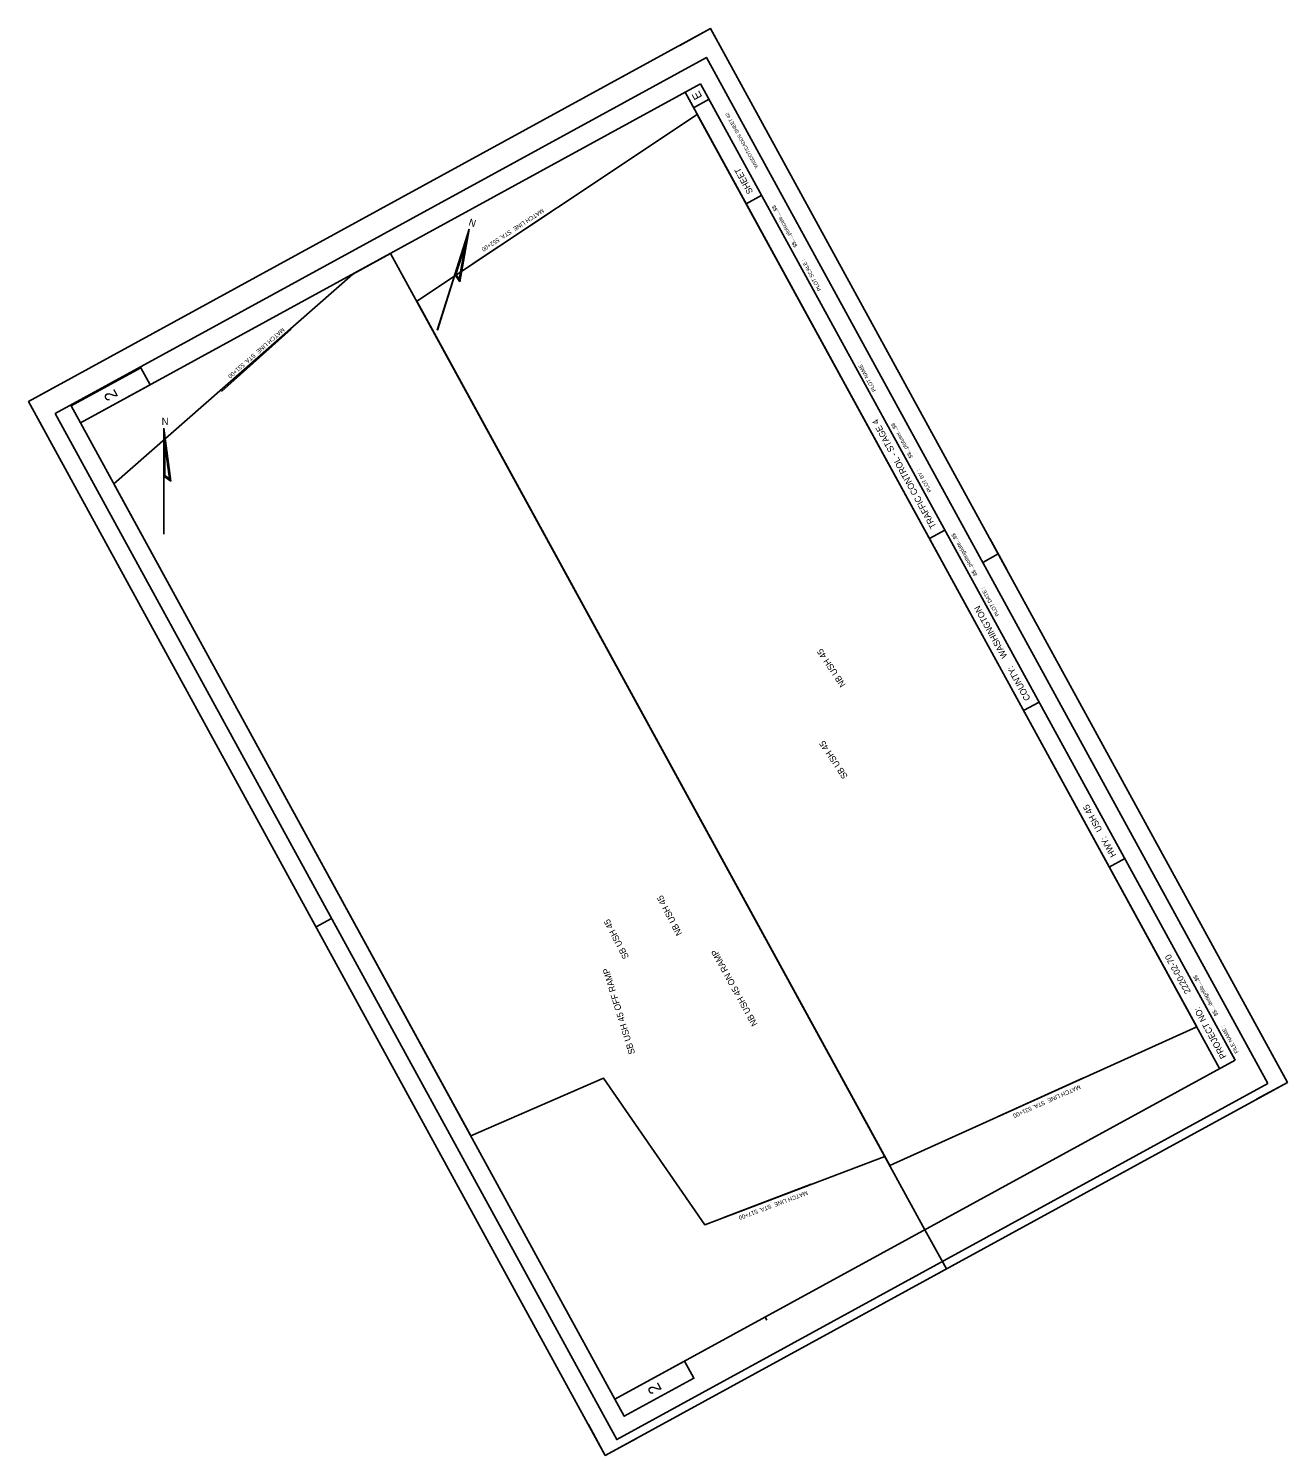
# Model space of a CAD drawing. Extents: x 358820 to 360601, y 175646 to 177665.
import ezdxf

# ---------------------------------------------------------------- set-up
doc = ezdxf.new("R2010")
doc.units = 0
for name, color, linetype in [('Default', 7, 'Continuous'), ('P_ALI_20', 7, 'Continuous'), ('P_ALI_200_Sta', 7, 'Continuous'), ('P_ALI_20_PIData', 7, 'Continuous'), ('P_ALI_20_Sta', 7, 'Continuous'), ('P_ALI_20_Tic', 7, 'Continuous'), ('P_ALI_50_Equation', 7, 'Continuous'), ('P_ALI_50_PIData', 7, 'Continuous'), ('P_ALI_50_Tic', 7, 'Continuous')]:
    doc.layers.add(name, color=color, linetype=linetype)

msp = doc.modelspace()

# ---------------------------------------------------------------- linework, layer by layer
msp.add_lwpolyline([(359635.8, 175645.7), (358819.8, 177137.1), (359784.8, 177665), (360600.8, 176173.7), (359635.8, 175645.7)])
at = {"layer": 'Default'}
for points in [[(360038.2, 176056.2), (360472.4, 176252.1), (359765.9, 177543.3), (359368.9, 177279.4)], [(360038.2, 176056.2), (360472.4, 176252.1), (359765.9, 177543.3), (359368.9, 177279.4)], [(360038.2, 176056.2), (360472.4, 176252.1), (359765.9, 177543.3), (359368.9, 177279.4)], [(359445.4, 176097.8), (359633.3, 176179.8), (359776.4, 175972.2), (360031.1, 176069), (359332, 177346.9), (359278.5, 177317.6), (358940.5, 177020.6)], [(359445.4, 176097.8), (359633.3, 176179.8), (359776.4, 175972.2), (360031.1, 176069), (359332, 177346.9), (359278.5, 177317.6), (358940.5, 177020.6)]]:
    msp.add_lwpolyline(points, close=True, dxfattribs=at)
at = {"layer": 'P_ALI_20'}
for p, q in [((359784.8, 177665), (359741, 177641)), ((359808.8, 177621.2), (359784.8, 177665)), ((359770.6, 177586.9), (358893.3, 177106.9)), ((360526.6, 176205.2), (359770.6, 177586.9)), ((360504.6, 176193.2), (359748.7, 177574.9)), ((359782.6, 177564.9), (359760.7, 177552.9)), ((359857, 177429), (359835.1, 177417)), ((360087.9, 175965.2), (359332, 177346.9)), ((358863.7, 177161.1), (358819.8, 177137.1)), ((358843.8, 177093.2), (358819.8, 177137.1)), ((359649.3, 175725.2), (358893.3, 177106.9)), ((360116.2, 176955.2), (360094.3, 176943.2)), ((360203.6, 176899.6), (360179.6, 176943.5)), ((360191.6, 176921.5), (360169.7, 176909.5)), ((360249.4, 176711.8), (360227.5, 176699.8)), ((360370.6, 176490.3), (360348.7, 176478.3)), ((359238.6, 176371.6), (359214.6, 176415.5)), ((359226.6, 176393.6), (359248.5, 176405.6)), ((360600.8, 176173.7), (360576.8, 176217.5)), ((360526.6, 176205.2), (359649.3, 175725.2)), ((360600.8, 176173.7), (360556.9, 176149.7)), ((360069.9, 175998.1), (360069.9, 175998.1)), ((360118.3, 175909.7), (360087.9, 175965.2)), ((360140.2, 175921.7), (360096.4, 175897.7)), ((359862, 175841.6), (359864.4, 175837.2)), ((359635.8, 175645.7), (359611.8, 175689.6)), ((359679.7, 175669.7), (359635.8, 175645.7))]:
    msp.add_line(p, q, dxfattribs=at)
for points in [[(358893.3, 177106.9), (358880.1, 177131), (358978.8, 177185), (358992, 177160.9)], [(359649.3, 175725.2), (359662.5, 175701.1), (359761.2, 175755), (359748, 175779.2)]]:
    msp.add_lwpolyline(points, close=True, dxfattribs=at)
at = {"layer": 'P_ALI_200_Sta'}
msp.add_line((360087.9, 175965.2), (359332, 177346.9), dxfattribs=at)
at = {"layer": 'P_ALI_20_PIData'}
for p, q in [((359422.8, 177316.8), (359443.1, 177381.2)), ((359430.1, 177306.7), (359443.1, 177381.2)), ((359423.6, 177317), (359440.4, 177370.2)), ((359429.7, 177308.5), (359440.4, 177370.2)), ((359424.5, 177317.1), (359437.8, 177359.2)), ((359429.2, 177310.4), (359437.8, 177359.2)), ((359398, 177238.1), (359422.8, 177316.8)), ((359398.2, 177238.1), (359423, 177316.6)), ((359422.8, 177316.8), (359430.1, 177306.7)), ((359423.6, 177317), (359429.7, 177308.5)), ((359424.5, 177317.1), (359429.2, 177310.4)), ((359021.2, 177024.3), (359011.2, 177099.3)), ((359011.2, 177031.7), (359011.2, 177099.3)), ((359011.9, 177032.1), (359011.9, 177088)), ((359020.2, 177025.9), (359011.9, 177088)), ((359012.7, 177032.5), (359012.7, 177076.7)), ((359019.2, 177027.6), (359012.7, 177076.7)), ((359011.2, 177031.7), (359021.2, 177024.3)), ((359011.2, 176949.3), (359011.2, 177031.7)), ((359011.4, 176949.3), (359011.4, 177031.6)), ((359011.9, 177032.1), (359020.2, 177025.9)), ((359012.7, 177032.5), (359019.2, 177027.6))]:
    msp.add_line(p, q, dxfattribs=at)
for points in [[(359443.1, 177381.1), (359443.1, 177381.1)], [(359011.2, 177099.2), (359011.2, 177099.2)]]:
    msp.add_lwpolyline(points, dxfattribs=at)
at = {"layer": 'P_ALI_20_Sta'}
msp.add_lwpolyline([(359445.4, 176097.8), (359633.3, 176179.8), (359776.4, 175972.2), (360031.1, 176069), (359332, 177346.9), (359278.5, 177317.6), (358940.5, 177020.6)], close=True, dxfattribs=at)
at = {"layer": 'P_ALI_20_Tic'}
msp.add_lwpolyline([(359635.8, 175645.7), (358819.8, 177137.1), (359784.8, 177665), (360600.8, 176173.7)], close=True, dxfattribs=at)
at = {"layer": 'P_ALI_50_Equation'}
for p, q in [((359448.9, 177332.5), (359559.1, 177405.8)), ((359092.6, 177151.4), (359191.2, 177239.6)), ((360191.7, 176125.5), (360312.3, 176179.9)), ((359803.5, 175982.5), (359927.2, 176029.5))]:
    msp.add_line(p, q, dxfattribs=at)
at = {"layer": 'P_ALI_50_Tic'}
for points in [[(360600.8, 176173.7), (359784.8, 177665), (358819.8, 177137.1), (359635.8, 175645.7)], [(360573.1, 176172.2), (359778.7, 177624.1), (358857.6, 177120.1), (359652, 175668.2)]]:
    msp.add_lwpolyline(points, close=True, dxfattribs=at)

# ---------------------------------------------------------------- texts
at = {"layer": 'P_ALI_20'}
for s, height, p in [('E', 12, (359773.2, 177568.4)), ('WISDOT/CADDS SHEET 42', 5, (359852.1, 177469.2)), ('SHEET ', 9, (359845.2, 177433.9)), ('$$.....plotscale.....$$', 5.4, (359907.8, 177357)), ('PLOT SCALE : ', 5.4, (359941.5, 177295.4)), ('PLOT NAME :                      ', 5.4, (360018.9, 177152.8)), ('2', 17.5, (358946.9, 177144.4)), ('TRAFFIC CONTROL - STAGE 4', 9, (360104.4, 176960.2)), ('$$...plotuser...$$', 5.4, (360071, 177058.7)), ('PLOT BY :', 5.4, (360097.4, 177010.5)), ('$$...plottingdate...$$', 5.4, (360162.2, 176892)), ('PLOT DATE :', 5.4, (360193.4, 176835)), (' WASHINGTON', 9, (360206.4, 176773.7)), ('COUNTY:', 9, (360237.6, 176716.7)), (' USH 45', 9, (360340.8, 176528.1)), ('HWY:', 9, (360358.8, 176495.2)), (' 2220-02-70', 9, (360466, 176299.1)), ('$$....designfile....$$', 5.4, (360503, 176269.2)), ('PROJECT NO:', 9, (360514.8, 176210.1)), ('FILE NAME :', 5.4, (360531.8, 176216.5)), ('2', 17.5, (359716.1, 175738.6))]:
    msp.add_text(s, height=height, rotation=118.6843, dxfattribs=at).set_placement(p)
at = {"layer": 'P_ALI_20_PIData'}
msp.add_text('N', height=10, rotation=342.4901, dxfattribs=at).set_placement((359441.6, 177386.8))
msp.add_text('N', height=10, dxfattribs=at).set_placement((359008.1, 177104.2))
at = {"layer": 'P_ALI_50_PIData'}
for s, height, rotation, p in [('MATCH LINE  STA. 552+00', 6, 213.2023, (359546.6, 177410.6)), ('MATCH LINE  STA. 531+00', 6, 221.3905, (359178.9, 177242.1)), ('NB USH 45', 9, 123.5762, (359976.4, 176736.6)), ('SB USH 45', 9, 123.5762, (359979.3, 176607)), ('NB USH 45', 9, 117.4057, (359744.8, 176384.2)), ('SB USH 45', 9, 117.4057, (359669.5, 176351.1)), ('NB USH 45 ON RAMP', 9, 118.7464, (359851.5, 176256.2)), ('SB USH 45 OFF RAMP', 9, 107.1355, (359678, 176214.9)), ('MATCH LINE  STA. 531+00', 6, 203.8807, (360306.5, 176170.4)), ('MATCH LINE  STA. 517+00', 6, 200.4031, (359920.8, 176020.4))]:
    msp.add_text(s, height=height, rotation=rotation, dxfattribs=at).set_placement(p)

doc.saveas('drawing.dxf')
